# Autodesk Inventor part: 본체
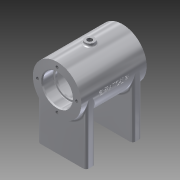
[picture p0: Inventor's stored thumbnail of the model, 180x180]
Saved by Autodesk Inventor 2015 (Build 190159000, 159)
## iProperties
Created: 2020-07
Part Number: 본체
Material: 알루미늄 6061
Document SubType Name: Modeling
Designer: 1015698
Density: 2.7 g/cm^3
Appearance: 알루미늄 - 평지
Mass: 305.265 g
Surface Area: 357.564 cm^2
Volume: 113.061 cm^3
Author: 1015698
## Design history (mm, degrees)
sketch "스케치1"
  geometry: L1 (-35, 0)-(35, 0); L2 (-35, 0)-(35, 0); L3 (35, 0)-(35, 26); L4 (35, 26)-(-35, 26); L5 (-35, 26)-(-35, 0); L6 (-35, 0)-(-23, 0); L7 (-23, 0)-(-23, 16); L8 (-23, 16)-(-35, 16); L9 (-35, 16)-(-35, 0); L10 (-23, 0)-(-21, 0); L11 (-21, 0)-(-21, 14); L12 (-21, 14)-(-23, 14); L13 (-23, 14)-(-23, 0); L14 (-21, 0)-(21, 0); L15 (21, 0)-(21, 21); L16 (21, 21)-(-21, 21); L17 (-21, 21)-(-21, 0); L18 (21, 0)-(23, 0); L19 (23, 0)-(23, 14); L20 (23, 14)-(21, 14); L21 (21, 14)-(21, 0); L22 (23, 0)-(35, 0); L23 (35, 0)-(35, 16); L24 (35, 16)-(23, 16); L25 (23, 16)-(23, 0); 2 further points
  constraints: 50 end point, 12 parallel, 7 horizontal, 6 perpendicular, 1 coincident, 1 midpoint, 1 point on line
  dimensions: "d0" = 70 distance of L1.start L1.end; "d1" = 52 diameter of L4 L1; "d2" = 12 distance of L7.end L8.end; "d3" = 12 distance of L23.end L24.end; "d4" = 2 distance of L11.end L12.end; "d5" = 42 distance of L15.end L16.end; "d6" = 2 distance of L19.end L20.end; "d7" = 28 diameter of L12 L1; "d8" = 28 diameter of L20 L1; "d9" = 32 diameter of L24 L1; "d10" = 32 diameter of L8 L1; "d11" = 42 diameter of L16 L1
revolve "회전1" sketch "스케치1" stored, may be unused: angle "d12" = 90 deg
fillet "모깎기1" dims "d13" = 0.3, "d14" = 3
sketch "스케치2" dims "d15" = 42
  geometry: C1 r 16 at (0, 0) reference; C2 r 26 at (0, 0) reference; 2 further points
  constraints: 2 vertical alignment, 1 coincident, 2 other
hole "구멍1" sketch "스케치2" at (0, 21) diameter "d16" = 3.242; stored, may be unused: countersink angle "d20" = 90 deg, drill point angle "d22" = 118 deg; dims "d17" = 8, "d18" = 4, "d19" = 2, "d21" = 10
node "작업 평면1"
sketch "스케치3"
  geometry: L1 (-64, -26)-(-64, 26); L2 (-64, 26)-(0, 26); L3 (0, -26)-(-64, -26); A1 r 26 centre (0, 0) between (0, 26) and (0, -26) reference; 1 further point
  constraints: 6 end point, 2 point on circle, 1 horizontal, 1 tangent
  dimensions: "d28" = 52 distance of L1.start L1.end; "d29" = 52 distance between parallel lines of L2 L3; "d30" = 64 distance from line of point (0, 0) L1
extrude "돌출1" join sketch "스케치3" distance "d31" = 10; taper "d32" = 0 deg
sketch "스케치4"
  geometry: L1 (0, 52)-(0, 0) reference; L2 (-10, 52)-(-10, 0) reference; L3 (-10, 26)-(-10, 46); L4 (-10, 46)-(0, 46); L5 (0, 0)-(0, 52) reference; L6 (-10, 26)-(-10, 6); L7 (-10, 6)-(0, 6); L8 (-5, 48.621)-(-5, 45.379) reference; 3 further points
  constraints: 8 end point, 5 point on line, 3 midpoint, 2 perpendicular
  dimensions: "d33" = 20 distance of L3.start L3.end; "d34" = 20 distance of L3.start L6.end
hole "구멍2" sketch "스케치4" at (-5, 6), (-5, 46) diameter "d35" = 4.134; stored, may be unused: countersink angle "d39" = 90 deg, drill point angle "d41" = 118 deg; dims "d36" = 8, "d37" = 4, "d38" = 2, "d40" = 10
node "작업 평면2"
sketch "스케치5"
  geometry: C1 r 5 at (0, 0); 1 further point
  constraints: 1 centre point, 1 coincident
  dimensions: "d43" = 10 diameter of C1
extrude "돌출2" join sketch "스케치5" stored distance "d44" = 10; taper "d45" = 0 deg
hole "구멍3" diameter "d48" = 5.188; stored, may be unused: countersink angle "d52" = 90 deg, drill point angle "d54" = 118 deg; dims "d46" = 10, "d47" = 10, "d49" = 12, "d50" = 4, "d51" = 2, "d53" = 16
sketch "스케치6"
  geometry: L1 (0, 0)-(-43.955, 0); L2 (0, 0)-(-27.251, -9.919)
  constraints: 4 end point, 1 horizontal
  dimensions: "d55" = 29 distance of L1.start L2.end; "d56" = 20 deg angle of L2 L1
node "작업 평면3"
sketch "스케치7"
  geometry: C1 r 6 at (0, 0); 1 further point
  constraints: 1 centre point, 1 coincident
  dimensions: "d57" = 12 diameter of C1
extrude "돌출3" join sketch "스케치7" stored distance "d58" = 10; taper "d59" = 0 deg
hole "구멍4" diameter "d62" = 5.188; stored, may be unused: countersink angle "d66" = 90 deg, drill point angle "d68" = 118 deg; dims "d60" = 10, "d61" = 10, "d63" = 12, "d64" = 4, "d65" = 2, "d67" = 16
node "작업 평면4"
sketch "스케치8"
  geometry: L1 (-35, -26)-(-35, 26) reference; L2 (-35, 26)-(35, 26) reference; 2 further points
  constraints: 1 other
  dimensions: "d70" = 35 distance from line of L1 point (0, 0); "d71" = 26 distance from line of L2 point (0, 0)
feature "엠보싱1" sketch "스케치8" dims "d10" = 32, "d72" = 0.5, "d73" = 0
chamfer "모따기1" distance "d74" = 1; stored, may be unused: second distance "d75" = 2, angle "d76" = 45 deg
fillet "모깎기2" dims "d77" = 2, "d78" = 3
node "솔리드1"
pattern_circular "원형 패턴1" dims angle "d24" = 360 deg
mirror "대칭1"
mirror "대칭2"
other parameters: "d42" = 29
